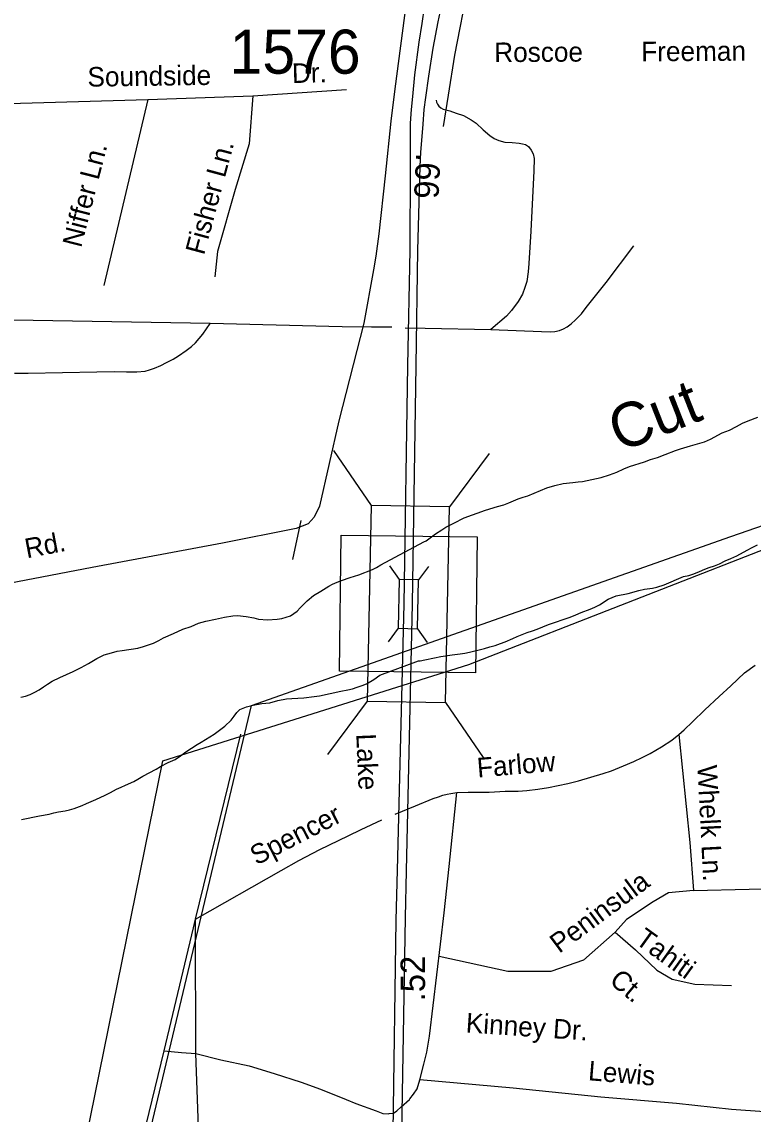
# Model space of a CAD drawing. Extents: x 1945482 to 2853149, y 66427 to 1015778.
# Drawn here: x 2332051 to 2334503, y 111441 to 115103 of the extents above; entities that cross this region are included whole.
import ezdxf

# ---------------------------------------------------------------- set-up
doc = ezdxf.new("R2010")
doc.units = 0
for name, color, linetype in [('Old_Level_10', 7, 'Continuous'), ('Old_Level_11', 7, 'Continuous'), ('Old_Level_17', 7, 'Continuous'), ('Old_Level_21', 7, 'Continuous'), ('Old_Level_28', 7, 'Continuous'), ('Old_Level_31', 7, 'Continuous'), ('Old_Level_32', 7, 'Continuous'), ('Old_Level_35', 7, 'Continuous'), ('Old_Level_48', 7, 'Continuous'), ('Old_Level_49', 7, 'Continuous'), ('Old_Level_50', 7, 'Continuous'), ('Old_Level_6', 7, 'Continuous'), ('Old_Level_60', 7, 'Continuous'), ('Old_Level_8', 7, 'Continuous')]:
    doc.layers.add(name, color=color, linetype=linetype)

msp = doc.modelspace()

# ---------------------------------------------------------------- linework, layer by layer
at = {"layer": 'Old_Level_28'}
for points in [[(2333361.7, 113152.1), (2333373.2, 113951.5), (2333379.3, 114337.3), (2333387, 114618.6), (2333389.4, 114666.8), (2333393.1, 114718.5), (2333397, 114759.8), (2333400.8, 114809.2), (2333405.4, 114849.2), (2333415.8, 114921.7), (2333430, 115015.2), (2333446.9, 115102.8), (2333460.7, 115165.8), (2333477.6, 115244.2), (2333493, 115301), (2333506.1, 115354), (2333556, 115556.2), (2333576, 115633.1), (2333629.7, 115857.5), (2333708.6, 116156.8), (2333764.2, 116385.2)], [(2333697, 116380.3), (2333639, 116128.3), (2333580.6, 115908.2), (2333529.9, 115693), (2333482.3, 115503.9), (2333453.9, 115384.4), (2333442, 115338.6), (2333425.4, 115268.8), (2333416.2, 115239.6), (2333406.5, 115195), (2333400.2, 115151.5), (2333392.2, 115097.7), (2333382.4, 115035.1), (2333367.4, 114925.4), (2333361.2, 114853.2), (2333356.7, 114809.5), (2333353.5, 114763.8), (2333353.5, 114725.4), (2333353.2, 114617.1), (2333351.7, 114337.3), (2333344, 113951.5), (2333332.6, 113150.6)], [(2333332.6, 113150.6), (2333310.2, 112258.9), (2333305.6, 112091.4), (2333294.8, 111382.8), (2333291.8, 111229.1), (2333265.8, 110943.9), (2333262.7, 110720.2), (2333271.7, 110519.6)], [(2333311.2, 110642.8), (2333303.9, 110765.6), (2333296.7, 110968.7), (2333325.6, 111379.7), (2333337.8, 112100.6), (2333340.9, 112257.4), (2333361.7, 113152.1)]]:
    msp.add_lwpolyline(points, dxfattribs=at)
at = {"layer": 'Old_Level_31'}
msp.add_lwpolyline([(2333577.9, 113376.7), (2333572.7, 112920.8), (2333116.5, 112926), (2333121.6, 113381.9)], close=True, dxfattribs=at)
at = {"layer": 'Old_Level_32'}
for points in [[(2333697, 116380.3), (2333643.2, 116378.2), (2333632.8, 116374.3), (2333627.7, 116369.3), (2333614.9, 116346.3), (2333605.9, 116323.7), (2333510.5, 115946.9), (2333426.7, 115592.6), (2333379.1, 115392.4), (2333354.7, 115282.5), (2333347.7, 115231.8), (2333339.7, 115166.9), (2333302.3, 114878.8), (2333288.4, 114770), (2333269.2, 114587.1), (2333248.2, 114392.7), (2333237.8, 114317.6), (2333230.5, 114271.5), (2333198.5, 114092.9), (2333113.8, 113765.3), (2333049.4, 113479.8)], [(2333839.5, 116365.4), (2333719.4, 115889.2), (2333632.1, 115552.3), (2333547.5, 115227.4), (2333502.2, 114991.8), (2333481.2, 114857.4), (2333463.8, 114752.7)], [(2333049.4, 113479.8), (2333031.3, 113443.2), (2333011.6, 113419.9), (2332970.9, 113404.8), (2332724.3, 113355.8), (2332286.8, 113273.9), (2331476.7, 113118.6), (2331075.9, 113033.9), (2330776.7, 112985.9), (2330640.9, 112964.1), (2330495.5, 112948.9), (2330380.3, 112935.5), (2330206.5, 112906.5), (2330117.5, 112897.7), (2330014.6, 112897.7), (2329890.7, 112904.7)]]:
    msp.add_lwpolyline(points, dxfattribs=at)
at = {"layer": 'Old_Level_35'}
for p, q in [((2333125.3, 114080.7), (2332683.1, 114091.8)), ((2333223.7, 114080), (2333125.3, 114080.7)), ((2333291.4, 114079.5), (2333223.7, 114080)), ((2333336.4, 114077.9), (2333404.1, 114076.5)), ((2333404.1, 114076.5), (2333623.6, 114071.8)), ((2332959.5, 113300.5), (2332988.1, 113431)), ((2332634.2, 112094.9), (2332785.7, 112714.7)), ((2333303.3, 112446.4), (2333371.5, 112474.8)), ((2333189.6, 112395.2), (2333257.9, 112427.4)), ((2332528.9, 111653.6), (2332627.4, 112066.2)), ((2332627.4, 112066.2), (2332634.2, 112094.9)), ((2332634.2, 112066.6), (2332634.2, 112094.9)), ((2332634.6, 111645), (2332634.2, 112066.6)), ((2333171.7, 111477.3), (2333238.9, 111451.8)), ((2333238.9, 111451.8), (2333261.2, 111443.2))]:
    msp.add_line(p, q, dxfattribs=at)
for points in [[(2331736.3, 114821.6), (2332474.2, 114842.8), (2332826.2, 114855.6)], [(2332826.2, 114855.6), (2332813.5, 114694.3), (2332766.9, 114541.5), (2332707.5, 114333.6), (2332699, 114248.7)], [(2332826.2, 114855.6), (2333140.1, 114876.8)], [(2332474.2, 114842.8), (2332325.8, 114219)], [(2333440.4, 114840.3), (2333441.5, 114833.9), (2333445.4, 114826.8), (2333449.9, 114820.1), (2333456, 114815.1), (2333463.8, 114810.2), (2333486, 114804.5), (2333508, 114796.8), (2333531.9, 114788.9), (2333558, 114775.2), (2333574.6, 114763.3), (2333598.4, 114741.6), (2333620.9, 114721.8), (2333635, 114711.9), (2333651, 114705.6), (2333671, 114700.2), (2333695, 114698.5), (2333718.7, 114696.2), (2333729.9, 114694.6), (2333739.9, 114692.4), (2333750.3, 114684.9), (2333759.6, 114673.5), (2333765.7, 114661.3), (2333769.6, 114645.3), (2333768, 114603.3), (2333758.3, 114401), (2333751.4, 114293.1), (2333749.5, 114265.1), (2333744.2, 114232.8), (2333738.1, 114212.8), (2333730.5, 114190.5), (2333715.4, 114165.3), (2333693.6, 114135.2), (2333676, 114116.2), (2333623.6, 114071.8)], [(2333623.6, 114071.8), (2333793.8, 114065.4), (2333823.7, 114063.9), (2333838.8, 114064.8), (2333854.1, 114069), (2333867.6, 114074.2), (2333880.2, 114080.6), (2333893.6, 114090.6), (2333907.5, 114104.3), (2333927.4, 114124.8), (2333943, 114145.1), (2334010.2, 114229.8), (2334102.8, 114352.6)], [(2332683.1, 114091.8), (2332022.9, 114103.1)], [(2332026.7, 113925), (2332054.9, 113925.5), (2332072.6, 113925.5), (2332302.8, 113930), (2332360.9, 113930.7), (2332402, 113929.7), (2332436.8, 113929.4), (2332464.9, 113932.2), (2332479.2, 113936.3), (2332496.7, 113942), (2332517.7, 113950.7), (2332536.6, 113960.9), (2332558.5, 113972.6), (2332576.1, 113983.5), (2332602.3, 114000.9), (2332620.1, 114015.1), (2332634.1, 114027.5), (2332657.9, 114056.6), (2332683.1, 114091.8)], [(2333509.9, 112520.1), (2333547.9, 112520.3), (2333617.8, 112521.1), (2333671.8, 112523.8), (2333715.8, 112524.3), (2333744.9, 112526.4), (2333781.8, 112530.8), (2333816.8, 112536.1), (2333850, 112542.7), (2333881.9, 112549.5), (2333917.6, 112558.2), (2333959.5, 112570.6), (2334000, 112583.1), (2334027.9, 112592.7), (2334068.9, 112609.1), (2334103.1, 112623.2), (2334130.8, 112636.5), (2334158.5, 112650.7), (2334196.3, 112673.2), (2334230.3, 112695.5), (2334254.1, 112713.9), (2334271.9, 112730), (2334299.4, 112756), (2334341.1, 112796.7), (2334388.9, 112841), (2334428.5, 112877.7), (2334474.4, 112920.8), (2334509.5, 112946.2)], [(2334254.1, 112713.9), (2334291.1, 112352.4)], [(2333371.5, 112474.8), (2333430.3, 112499.2), (2333448.1, 112505.5), (2333462.6, 112511), (2333477.9, 112513.6), (2333490, 112516), (2333509.9, 112520.1)], [(2333467, 112116.4), (2333484.5, 112271.6), (2333509.9, 112520.1)], [(2332634.2, 112094.9), (2332920.6, 112257.9), (2332979.6, 112291.7), (2333050.1, 112328), (2333145.4, 112374.4), (2333189.6, 112395.2)], [(2334291.1, 112352.4), (2334303.8, 112191.2), (2334677, 112199.7), (2334677, 112017.2), (2334694, 111894.1), (2334736.4, 111843.2), (2334846.7, 111796.5), (2334982.4, 111796.5), (2335079.9, 111838.9), (2335164.7, 111911.1), (2335228.3, 111957.8), (2335283.5, 111970.5), (2335372.5, 111945), (2335436.2, 111906.8), (2335521, 111877.1), (2335597.3, 111877.1), (2335682.1, 111902.6)], [(2334303.8, 112191.2), (2334219, 112182.7), (2334168.1, 112153), (2334079, 112093.6), (2334040.9, 112051.1), (2334108.7, 111991.7), (2334180.8, 111923.8), (2334231.7, 111894.1), (2334308, 111877.1), (2334431, 111872.9)], [(2333386.1, 111556.5), (2333399.4, 111608.5), (2333409, 111648.6), (2333418.4, 111702.8), (2333455.1, 112011.5), (2333467, 112116.4)], [(2334040.9, 112051.1), (2333934.8, 111957.8), (2333824.6, 111919.6), (2333680.4, 111919.6)], [(2333680.4, 111919.6), (2333450.4, 111970.2)], [(2332154.7, 110123.1), (2332317.7, 110791.3), (2332448.1, 111322.9), (2332528.9, 111653.6)], [(2332528.9, 111653.6), (2332586.9, 111648.3), (2332634.6, 111645)], [(2332634.6, 111645), (2332719.1, 111623.7), (2332813.2, 111602.8), (2332897.9, 111577.3), (2332987.9, 111548.3), (2333052.2, 111524.9), (2333138.6, 111489.9), (2333171.7, 111477.3)], [(2333226.4, 110089.2), (2333182.5, 110158), (2333151.5, 110236.5), (2332924.1, 110587.4), (2332818, 110782.4), (2332789.4, 110832.2), (2332754.7, 110906), (2332727.8, 110971.5), (2332707.3, 111025.2), (2332683.9, 111102.7), (2332667.7, 111171), (2332656.1, 111231.6), (2332650.7, 111278.7), (2332645.9, 111332.6), (2332640.3, 111490.9), (2332634.6, 111645)], [(2333352.5, 111492.4), (2333365, 111507.7), (2333376.4, 111526.6), (2333386.1, 111556.5)], [(2334726.2, 111440), (2334673.3, 111441.5), (2334625.6, 111443.3), (2334602.6, 111444.3), (2334541.4, 111448.5), (2334431.1, 111457.2), (2334246.8, 111477.2), (2333992.6, 111498.7), (2333698.4, 111527.8), (2333386.1, 111556.5)], [(2333323, 111466), (2333350.6, 111490.1), (2333352.5, 111492.4)], [(2333261.2, 111443.2), (2333280, 111442.3), (2333283.5, 111442.9)], [(2333283.5, 111442.9), (2333297.6, 111445), (2333308.4, 111452.6), (2333323, 111466)]]:
    msp.add_lwpolyline(points, dxfattribs=at)
at = {"layer": 'Old_Level_48'}
for points in [[(2332524.3, 112625.8), (2333550.6, 112948.9), (2334660.6, 113382.2)], [(2331143, 105650.7), (2331813.7, 108175.7), (2331620.1, 108251.3), (2331719.7, 108667.4), (2332524.3, 112625.8)]]:
    msp.add_lwpolyline(points, dxfattribs=at)
at = {"layer": 'Old_Level_49'}
msp.add_lwpolyline([(2330352.2, 107963.5), (2330441, 107913.5), (2331723.1, 108557.6), (2331795.2, 108507.7), (2332821.9, 112811.2), (2334428.6, 113377.6), (2334989.1, 113572)], dxfattribs=at)
at = {"layer": 'Old_Level_50'}
for p, q in [((2333096, 113666.1), (2333222.4, 113481.9)), ((2333618.4, 113655.8), (2333484.8, 113476.8)), ((2333284.4, 113280), (2333316, 113234)), ((2333415, 113277.5), (2333381.6, 113232.7)), ((2333312.7, 113070), (2333279.4, 113025.2)), ((2333378.3, 113068.7), (2333410, 113022.7)), ((2333209.5, 112825.9), (2333076, 112646.9)), ((2333471.9, 112820.8), (2333598.3, 112636.6))]:
    msp.add_line(p, q, dxfattribs=at)
msp.add_lwpolyline([(2333471.9, 112820.8), (2333484.8, 113476.8), (2333222.4, 113481.9), (2333209.5, 112825.9)], close=True, dxfattribs=at)
msp.add_lwpolyline([(2333378.3, 113068.7), (2333381.6, 113232.7), (2333316, 113234), (2333312.7, 113070), (2333378.3, 113068.7)], dxfattribs=at)
at = {"layer": 'Old_Level_60'}
for points in [[(2332302.5, 112969.1), (2332327, 112981), (2332352.2, 112988.2), (2332371.2, 112993), (2332387.5, 112995.7), (2332440.5, 113003), (2332459.7, 113008.7), (2332492.7, 113020.2), (2332511.2, 113029.2), (2332526.5, 113037.6), (2332559.5, 113052.2), (2332591.7, 113067.3), (2332619, 113076.2), (2332643.7, 113087), (2332668, 113093.8), (2332700.2, 113101.2), (2332730.7, 113107.7), (2332759.2, 113111.4), (2332774.7, 113112.5), (2332804, 113109.7), (2332829.5, 113105), (2332845, 113101.2), (2332875, 113098.5), (2332907.7, 113101.2), (2332922.7, 113102.9), (2332952, 113112.4), (2332975, 113127.8), (2332985, 113139.1), (2333007.5, 113162.3), (2333029, 113179.6), (2333053.5, 113194.3), (2333080.2, 113211.3), (2333093.5, 113218.6), (2333108.7, 113224.8), (2333123.7, 113230.4), (2333152.5, 113240.2), (2333181.7, 113249.6), (2333226.7, 113267), (2333241, 113273.8), (2333255, 113282.7), (2333399.2, 113360.4), (2333406.5, 113363.6), (2333438.5, 113386.3), (2333459.7, 113399.7), (2333473, 113408.9), (2333499.5, 113422.9), (2333534.5, 113440), (2333605.5, 113466.3), (2333646.7, 113478.5), (2333667.5, 113484.1), (2333684.5, 113490.9), (2333700.2, 113498), (2333715.7, 113504.3), (2333732.5, 113509.2), (2333748, 113514.4), (2333811.7, 113541.3), (2333838.7, 113549.1), (2333866.5, 113555.1), (2333899.2, 113559.4), (2333916.2, 113560.7), (2333931.5, 113562.8), (2333963, 113568.5), (2333994.2, 113575.8), (2334021.5, 113584.1), (2334046.2, 113594.1), (2334070, 113605.1), (2334088.2, 113612.7), (2334139.2, 113628.4), (2334158.7, 113635.8), (2334182.2, 113642.9), (2334208, 113652.3), (2334243.5, 113666.2), (2334259.7, 113671.6), (2334293.5, 113682.1), (2334316.7, 113688), (2334340.7, 113695), (2334360.5, 113704.6), (2334399.5, 113725.6), (2334423.5, 113734.7), (2334447, 113746.4), (2334467.5, 113757.6), (2334486.2, 113765.2), (2334519.2, 113777.8)], [(2332211.2, 112461.1), (2332226.5, 112465.9), (2332254.2, 112475.6), (2332268.7, 112482.5), (2332284, 112488.9), (2332299.2, 112496.1), (2332331.2, 112510.4), (2332349.2, 112519.4), (2332369, 112530.3), (2332384, 112537.6), (2332398.7, 112543.9), (2332426.5, 112556.8), (2332440, 112564.1), (2332457, 112574.8), (2332501.5, 112598.2), (2332516.2, 112607.3), (2332542.2, 112619.8), (2332565, 112630.1), (2332583, 112642.8), (2332601.5, 112656.3), (2332639.5, 112680.8), (2332653.2, 112688.5), (2332696.5, 112715.4), (2332732, 112742.1), (2332753.7, 112762.3), (2332763.7, 112775), (2332772, 112787.7), (2332782.5, 112797.9), (2332804.2, 112807), (2332826.7, 112812.2), (2332856.2, 112817.8), (2332882.5, 112819.8), (2332910, 112827.6), (2332939.2, 112833.4), (2332957, 112835), (2332996.5, 112837.1), (2333031.2, 112841.5), (2333049, 112844.2), (2333085.5, 112852), (2333121, 112858.9), (2333144, 112863.7), (2333159.5, 112867.5), (2333175.2, 112872.2), (2333192.7, 112878.7), (2333206.7, 112884.2), (2333232, 112898.3), (2333252.2, 112913), (2333381.7, 112960.7), (2333387.2, 112961), (2333402.2, 112964.5), (2333435, 112971), (2333455.7, 112975.6), (2333494, 112980.6), (2333521.2, 112984.5), (2333537.2, 112987.1), (2333552.7, 112990.6), (2333602.7, 113002.8), (2333620.7, 113007.6), (2333638.5, 113012.8), (2333656.2, 113018.6), (2333672, 113024.9), (2333698, 113035.9), (2333712, 113042.7), (2333728.5, 113049.2), (2333746, 113055.8), (2333764, 113061.7), (2333778.7, 113067.7), (2333798, 113074.7), (2333817.5, 113082.8), (2333889.5, 113107.4), (2333909, 113115.3), (2333926.7, 113123.2), (2333957, 113134.1), (2333972.5, 113140.6), (2333987.7, 113148.7), (2334017.7, 113168.2), (2334043.5, 113178.5), (2334084.7, 113187), (2334120, 113197.1), (2334138.7, 113201.1), (2334165.5, 113204.6), (2334180.7, 113207.5), (2334205.5, 113216.1), (2334270, 113243.3), (2334288.2, 113247.3), (2334304.5, 113252.8), (2334323.5, 113261), (2334341, 113268), (2334356, 113273.5), (2334373.2, 113279.2), (2334391, 113286.5), (2334409, 113296.2), (2334428.2, 113304.6), (2334449, 113313.2), (2334483.7, 113331.5), (2334500.2, 113340.8), (2334517.5, 113349.7)], [(2332048.5, 112839.5), (2332063.5, 112843.1), (2332079.7, 112848.2), (2332094.5, 112855.5), (2332109.7, 112864.2), (2332123.5, 112874), (2332137.2, 112883), (2332153.2, 112892.5), (2332179.2, 112905.2), (2332224, 112925), (2332250.2, 112938.3), (2332275, 112951.9), (2332302.5, 112969.1)], [(2332050.7, 112429), (2332110.5, 112441.2), (2332143.2, 112447.2), (2332158.2, 112451.4), (2332174.5, 112454.5), (2332196.2, 112457.8), (2332211.2, 112461.1)]]:
    msp.add_lwpolyline(points, dxfattribs=at)

# ---------------------------------------------------------------- texts
at = {"layer": 'Old_Level_10'}
for s, rotation, p in [('Roscoe ', 0.3403, (2333635.4, 114968.3)), ('Freeman', 0.3403, (2334128.3, 114971)), ('Soundside ', 0.83, (2332271.9, 114885.9)), ('Dr.', 1.6202, (2332957.8, 114897.9)), ('Niffer Ln.', 75.6075, (2332250.1, 114343.6)), ('Fisher Ln.', 74.9183, (2332662, 114318.8)), ('Farlow', 4.8272, (2333580.1, 112569.7)), ('Whelk Ln.', 272.9328, (2334316.2, 112609.9)), ('Spencer', 27.2324, (2332838.3, 112274.3)), ('Peninsula', 36.6333, (2333853, 111978.4)), ('Tahiti', 324.2817, (2334104.4, 112016.1)), ('Ct.', 320.1755, (2334017.7, 111882.8)), ('Kinney Dr.', 356.2199, (2333538.5, 111715.2)), ('Lewis', 355.2598, (2333948.5, 111555.1))]:
    msp.add_text(s, height=65.62, rotation=rotation, dxfattribs=at).set_placement(p)
at = {"layer": 'Old_Level_11'}
msp.add_text('Rd.', height=65.62, rotation=10.8555, dxfattribs=at).set_placement((2332068.1, 113304.6))
at = {"layer": 'Old_Level_17'}
for s, rotation, p in [('.66', 267.0915, (2333373.9, 114664.8)), ('.52', 90.0533, (2333403.3, 111819.6))]:
    msp.add_text(s, height=82.02, rotation=rotation, dxfattribs=at).set_placement(p)
at = {"layer": 'Old_Level_21'}
msp.add_text('Cut', height=147.64, rotation=21.4619, dxfattribs=at).set_placement((2334055.4, 113659.3))
at = {"layer": 'Old_Level_6'}
msp.add_text('Lake', height=65.62, rotation=272.4275, dxfattribs=at).set_placement((2333172.6, 112715.9))
at = {"layer": 'Old_Level_8'}
msp.add_text('1576', height=147.64, dxfattribs=at).set_placement((2332748, 114929.4))

doc.saveas('drawing.dxf')
